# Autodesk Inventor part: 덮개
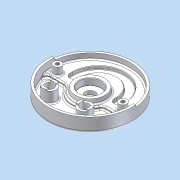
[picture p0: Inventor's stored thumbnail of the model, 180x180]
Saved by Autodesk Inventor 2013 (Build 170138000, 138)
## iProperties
Company: 한국ATC센터
Created: 2015-04
Part Number: 덮개
Document SubType Name: Modeling
Designer: KYOUNG IL JANG
Density: 2.71 g/cm^3
Material: 알루미늄-6061
Author: KYOUNG IL JANG
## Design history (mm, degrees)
sketch "스케치1"
  geometry: L1 (-59, -19)-(-59, 19); L2 (59, 19)-(59, -19); L3 (-41, 19)-(-41, -19); L4 (41, -19)-(41, 19); L5 (59, 5)-(41, 5); L6 (-41, 5)-(-59, 5); C1 r 90 at (0, 0); C2 r 95 at (0, 0); A1 r 59 centre (0, 19) between (59, 19) and (-59, 19); A2 r 59 centre (0, -19) between (-59, -19) and (59, -19); A3 r 41 centre (0, -19) between (-41, -19) and (41, -19); A4 r 41 centre (0, 19) between (41, 19) and (-41, 19); 2 further points
  constraints: 12 end point, 8 point on circle, 6 centre point, 4 point on line, 4 tangent, 2 parallel, 2 perpendicular, 1 coincident, 1 collinear, 1 horizontal alignment, 1 midpoint, 1 vertical, 1 vertical alignment, 3 other
  dimensions: "d2" = 180 diameter of C1; "d3" = 156 dimension on A2 A1; "d4" = 118 distance between parallel lines of L2 L1; "d5" = 18 distance between parallel lines of L2 L4; "d8" = 190 diameter of C2; "d121" = 5 distance from line of L5 point (0, 0)
extrude "돌출1" new body sketch "스케치1" distance "d6" = 14; taper "d7" = 0 deg
extrude "돌출2" join sketch "스케치1" distance "d9" = 13; taper "d10" = 0 deg
extrude "돌출3" cut sketch "스케치1" distance "d11" = 7; taper "d12" = 0 deg
sketch "스케치2"
  geometry: C1 r 11.5 at (0, 0); 1 further point
  constraints: 1 centre point, 1 coincident
  dimensions: "d13" = 23 diameter of C1
extrude "돌출4" cut sketch "스케치2" stored distance "d14" = 7; taper "d15" = 0 deg
fillet "모깎기1"
fillet "모깎기2"
sketch "스케치3"
  geometry: L1 (-89.658, 7.844)-(-94.638, 8.28); L2 (89.658, 7.844)-(94.638, 8.28); L3 (0, 0)-(0, -90); A1 r 95 centre (0, 0) between (-94.638, 8.28) and (94.638, 8.28) reference; A2 r 90 centre (0, 0) between (-89.658, 7.844) and (89.658, 7.844) reference; 1 further point
  constraints: 6 end point, 5 point on circle, 1 point on line, 1 vertical, 1 other
  dimensions: "d16" = 190 deg dimension on L2 L1
extrude "돌출5" join sketch "스케치3" distance "d17" = 5; taper "d18" = 0 deg
hole "구멍1" diameter "d21" = 50; stored, may be unused: countersink angle "d25" = 90 deg, drill point angle "d27" = 0 deg; dims "d19" = 10, "d20" = 10, "d22" = 6, "d23" = 4, "d24" = 2, "d26" = 5
fillet "모깎기3" dims "d28" = 0.3
fillet "모깎기5" dims "d30" = 3
sketch "스케치4"
  geometry: C1 r 35 at (0, 0); C2 r 25 at (0, 0); 1 further point
  constraints: 2 centre point, 1 coincident
  dimensions: "d32" = 70 diameter of C1 (derived); "d36" = 10 radial gap between concentric circles of C1 C2
extrude "돌출6" join sketch "스케치4" distance "d33" = 10; taper "d34" = 0 deg
feature "면 기울기2" dims angle "d37" = 10 deg
chamfer "모따기1" distance "d39" = 1; stored, may be unused: second distance "d40" = 2, angle "d41" = 45 deg
fillet "모깎기7" dims "d42" = 5
sketch "스케치5"
  geometry: L1 (-40.249, -12)-(-89.196, -12); L2 (40.249, -12)-(89.196, -12); A1 r 90 centre (0, 0) between (-89.196, -12) and (89.196, -12) reference; A2 r 42 centre (0, 0) between (-40.249, -12) and (40.249, -12); 1 further point
  constraints: 4 end point, 4 point on circle, 1 centre point, 1 collinear, 1 horizontal, 1 point on line
  dimensions: "d43" = 48 radial gap between concentric circles of A1 A2; "d44" = 12 distance from line of point (0, 0) L1
extrude "돌출7" cut sketch "스케치5" stored distance "d45" = 10; taper "d46" = 0 deg
fillet "모깎기8" dims "d47" = 10
chamfer "모따기2" distance "d49" = 1; stored, may be unused: second distance "d50" = 2, angle "d51" = 45 deg
sketch "스케치8"
  geometry: C1 r 9 at (74, 0); C2 r 9 at (-74, 0); A1 r 74 centre (0, 0) between (74, 0) and (-74, 0); 1 further point
  constraints: 3 centre point, 2 horizontal alignment, 2 point on circle, 1 coincident, 1 equal radius
  dimensions: "d64" = 18 diameter of C1; "d65" = 148 diameter of A1
extrude "돌출9" join sketch "스케치8" stored distance "d66" = 5; taper "d67" = 0 deg
sketch "스케치11"
  geometry: C1 r 15 at (40, -52); C2 r 15 at (-40, -52); 1 further point
  constraints: 2 centre point, 1 equal radius, 1 horizontal alignment
  dimensions: "d82" = 52 vertical distance of point (0, 0) C1.centre; "d83" = 30 diameter of C1; "d84" = 80 distance of C2.centre C1.centre; "d85" = 40 horizontal distance of point (0, 0) C1.centre (= 0.5 x d84)
extrude "돌출10" join sketch "스케치11" stored distance "d86" = 10; taper "d87" = 0 deg
node "구멍3"
node "구멍5"
hole "구멍6" diameter "d92" = 20; stored, may be unused: countersink angle "d96" = 90 deg, drill point angle "d98" = 118 deg; dims "d90" = 10, "d91" = 10, "d93" = 6, "d94" = 4, "d95" = 2, "d97" = 8
hole "구멍7" diameter "d101" = 20; stored, may be unused: countersink angle "d105" = 90 deg, drill point angle "d107" = 118 deg; dims "d99" = 10, "d100" = 10, "d102" = 6, "d103" = 4, "d104" = 2, "d106" = 8
fillet "모깎기13" dims "d108" = 3
sketch "스케치13"
  geometry: L1 (-20.252, -58)-(-26, -58); L2 (-42, -58)-(-47.748, -58); L3 (-20.252, -46)-(-26, -46); L4 (-42, -46)-(-47.748, -46); L5 (-108, -65.748)-(-108, -60); L6 (-108, -44)-(-108, -38.252); L7 (-120, -44)-(-120, -38.252); L8 (-120, -60)-(-120, -65.748); A1 r 15 centre (-34, -52) between (-20.252, -58) and (-47.748, -58) reference; A2 r 10 centre (-34, -52) between (-26, -58) and (-42, -58) reference; A3 r 15 centre (-114, -52) between (-108, -65.748) and (-108, -38.252) reference; A4 r 10 centre (-114, -52) between (-108, -60) and (-108, -44) reference; 1 further point
  constraints: 16 end point, 16 point on circle, 3 equal length, 3 point on line, 2 collinear, 1 horizontal, 1 perpendicular
  dimensions: "d114" = 12 distance between parallel lines of L4 L2; "d115" = 6 distance from line of A1.centre L2 (= 0.5 x d114); "d116" = 12 distance between parallel lines of L8 L5 (= d114); "d117" = 6 distance from line of A3.centre L5 (= d115)
extrude "돌출12" join sketch "스케치13" distance "d118" = 3; taper "d119" = 0 deg
fillet "모깎기14" dims "d120" = 1
node "솔리드1"
sketch "스케치9"
  geometry: 1 further point
hole "구멍2" sketch "스케치9" diameter "d68" = 8.376; stored, may be unused: countersink angle "d72" = 90 deg, drill point angle "d74" = 120 deg; dims "d69" = 16, "d70" = 4, "d71" = 2, "d73" = 21
sketch "스케치10"
  geometry: 1 further point
hole "구멍4" sketch "스케치10" diameter "d75" = 8.376; stored, may be unused: countersink angle "d79" = 90 deg, drill point angle "d81" = 120 deg; dims "d76" = 16, "d77" = 4, "d78" = 2, "d80" = 21
